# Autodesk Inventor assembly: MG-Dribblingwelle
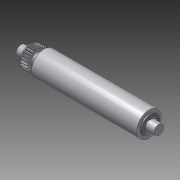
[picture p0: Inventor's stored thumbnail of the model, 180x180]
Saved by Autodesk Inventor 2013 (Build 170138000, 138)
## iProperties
Created: 2012-07
Part Number: MG-Dribblingwelle
Document SubType Name: Assembly
Designer: rYan
Mass: 30.4425 g
Surface Area: 91.3331 cm^2
Volume: 12.5097 cm^3
Density: 2.43351 g/cm^3
Author: rYan
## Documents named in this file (5)
- D:\SVN\2013\Inventor\Dribbling Device\MG-Dribblingwelle.iam
- D:\SVN\2013\Inventor\Dribbling Device\Dribblingwelle.ipt
- D:\SVN\2013\Inventor\Dribbling Device\Gummischlauch.ipt
- D:\SVN\2013\Inventor\Kaufteile\Zahnrad z24.ipt
- D:\SVN\2013\Inventor\Inhaltscenter\de-DE\DIN 6799\DIN 6799 - 5 6.ipt
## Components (5 placed, 4 different names)
1. Dribblingwelle:1 — Passend:1, Fluchtend:1, Passend:3, Passend:5, Passend:6, Passend:7
2. Gummischlauch:1 — Passend:1, Fluchtend:1
3. Zahnrad z=24:1 — Passend:6, Passend:7
4. DIN 6799 5:1 — Passend:3
5. DIN 6799 5:2 — Passend:5
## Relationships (6: Mate 5, Flush 1)
- Passend:1 [Mate]: Dribblingwelle:1 ↔ Gummischlauch:1
- Fluchtend:1 [Flush]: Dribblingwelle:1 ↔ Gummischlauch:1
- Passend:3 [Mate]: Dribblingwelle:1 ↔ DIN 6799 5:1
- Passend:5 [Mate]: Dribblingwelle:1 ↔ DIN 6799 5:2
- Passend:6 [Mate]: Dribblingwelle:1 ↔ Zahnrad z=24:1
- Passend:7 [Mate]: Dribblingwelle:1 ↔ Zahnrad z=24:1
